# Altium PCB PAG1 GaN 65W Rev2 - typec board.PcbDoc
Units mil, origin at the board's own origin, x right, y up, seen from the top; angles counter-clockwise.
Board outline 312.28 x 580.71 mil, 2 copper layers (Top Layer, Bottom Layer); 6 components, 7 nets, 33 pads, 10 vias.
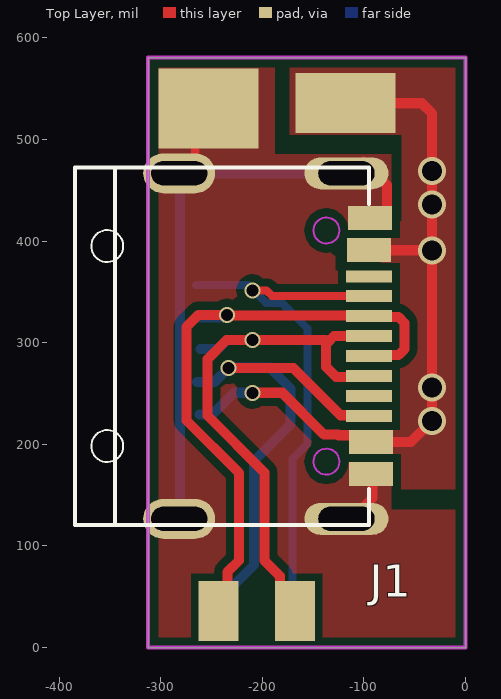
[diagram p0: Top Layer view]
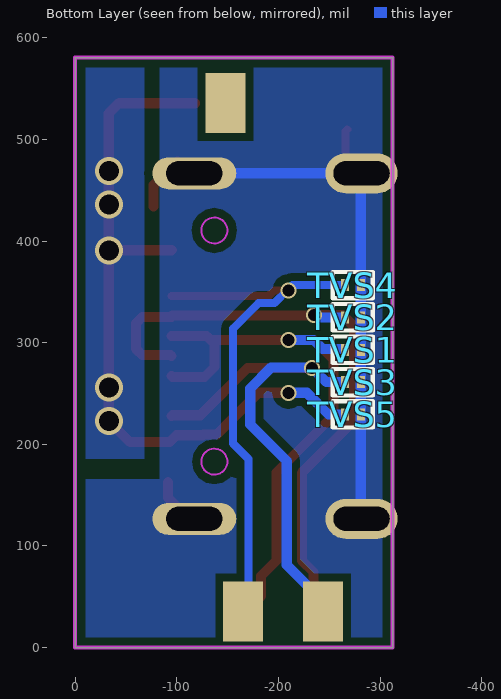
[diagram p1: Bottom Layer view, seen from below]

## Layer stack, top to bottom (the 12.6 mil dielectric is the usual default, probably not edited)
Top Solder: solder mask 0.4, Solder Resist, Dk 3.5
Top Layer: signal copper 1.4
Dielectric 1: dielectric 12.6, FR-4, Dk 4.8
Bottom Layer: signal copper 1.4
Bottom Solder: solder mask 0.4, Solder Resist, Dk 3.5

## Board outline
-312.28,0 -312.28,580.71 0,580.71 0,0

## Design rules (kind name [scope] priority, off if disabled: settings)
Clearance [All] p1: gap=8 ignorepadtopadclearanceinfootprint=FALSE
PlaneConnect [All] p1: planeconnectstyle=Direct reliefexpansion=20 reliefentries=4 reliefconductorwidth=10 reliefairgap=10
PolygonConnect [All] p1: connectstyle=Direct reliefconductorwidth=10 reliefentries=4 polygonreliefangle="90 Angle" airgapwidth=10
RoutingVias [All] p1: holewidth=28 width=50 viastyle="Through Hole" minholewidth=28 minwidth=50 maxholewidth=28 maxwidth=50
SolderMaskExpansion [All] p1: expansion=4 istentingtop=FALSE
UnRoutedNet [All] p1: checkbadconnections=TRUE
Width [All] p1: maxlimit=50 minlimit=6 preferedwidth=10 minimp=50.000000 maximp=50.000000 favimp=50.000000
28 further rules are at their usual default settings.

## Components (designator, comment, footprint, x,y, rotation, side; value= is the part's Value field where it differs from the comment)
J1 "" type-c3 -117.13,467.11 r180 top
TVS1 "ESD132 0201" W0201 -265.28,293.07 r180 bottom
TVS2 "ESD132 0201" W0201 -265.28,324.92 r180 bottom
TVS3 "ESD132 0201" W0201 -265.28,261.22 r180 bottom
TVS4 "ESD132 0201" W0201 -265.28,356.77 r180 bottom
TVS5 "ESD239 0201" W0201 -265.28,229.37 r180 bottom

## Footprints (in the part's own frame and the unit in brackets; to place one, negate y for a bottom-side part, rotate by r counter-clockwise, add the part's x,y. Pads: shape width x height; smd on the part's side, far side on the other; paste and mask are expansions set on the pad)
type-c3 [mm]
  rect 1.1x0.6 smd: A1(-0.588,1.129) A4(-0.563,1.929) B1(-0.613,7.529) B4(-0.613,6.729)
  rect 1.15x0.3 smd: A5(-0.563,3.079) A6(-0.563,4.079) A7(-0.563,4.579) A8(-0.563,5.579) B5(-0.563,6.079) B6(-0.563,5.079) B7(-0.563,3.579) B8(-0.563,2.594)
  oval 2.1x0.8 hole 0.6 slot 1.4 at 0 deg: MH1(0.002,8.649) MH4(0.002,0.009)
  oval 1.8x1 hole 0.6 slot 1.4 at 0 deg: MH2(4.182,8.649) MH3(4.182,0.009)
  Keep-Out Layer circle w0.05: c0.502,7.219 r0.325
  Keep-Out Layer circle w0.05: c0.502,1.439 r0.325
  silkscreen extent -0.57,-0.14 6.78,8.8
W0201 [mm]
  rect 0.2x0.3 smd mask+0.051: 1(0,0) 2(0.4,0)
  silkscreen extent -0.3,-0.33 0.7,0.33

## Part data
J1: library part USB-PD_TYPE-C_7
TVS1 TVS2 TVS3 TVS4 TVS5: library part "TVS Diode_1"

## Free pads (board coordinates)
  rect 98.43x78.74 smd: 0(-252.99,530.71)
  rect 39.37x59.06 smd far side: 0(-244.09,35.43) 0(-165.35,35.43) 0(-147.99,535.71)
  rect 39.37x59.06 smd: 0(-242.99,35.71) 0(-167.99,35.71)
  rect 98.43x59.06 smd: 0(-117.99,535.71)

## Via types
v1: diameter 27.56, hole 19.68, Top Layer to Bottom Layer, 5 vias
v2: diameter 15.75, hole 11.81, Top Layer to Bottom Layer, 5 vias

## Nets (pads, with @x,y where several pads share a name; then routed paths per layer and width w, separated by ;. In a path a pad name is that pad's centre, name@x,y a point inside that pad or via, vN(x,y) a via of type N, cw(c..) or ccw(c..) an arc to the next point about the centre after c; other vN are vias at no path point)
NetD16_K: J1.B5 pad.0@-244.09,35.43 TVS3.1 | length 513.6
  Top Layer w10: v2(-233.27,275.18) -169.59,275.18 -122.98,228.58 -95.74,228.58 J1.B5
  Bottom Layer w10: TVS3.1@-264.21,261.22 -247.23,261.22 v2(-233.27,275.18) ; pad.0@-244.09,35.43 -244.09,45.28 -208.17,81.2 -208.17,183.61 -172.24,219.54 -172.24,254.96 -192.99,275.71 v2@-233.27,275.71
NetD17_K: J1.A5 pad.0@-165.35,35.43 TVS4.1 | length 531.7
  Top Layer w7.87: v2(-209.8,351.46) -195.87,351.46 -190.31,345.91 J1.A5
  Bottom Layer w7.87: TVS4.1 -213.88,356.77 -209.19,352.08 -196.19,339.08 -194.05,339.08 -180.61,339.08 -155.31,313.77 -155.31,200.87 -170.48,185.69 -170.48,40.56 pad.0@-165.35,35.43
NetDM_1: J1.A7 J1.B7 pad.0@-242.99,35.71 TVS2.1 | length 622
  Top Layer w9.84: pad.0@-242.99,35.71 -234.47,44.23 -234.47,74.23 -222.99,85.71 -222.99,171.94 -274.61,223.55 -274.61,315.68 -262.82,327.47 v2(-234.87,327.47) -234.24,326.84 -95.58,326.84 J1.B7 ; J1.B7@-95.94,326.22 -94.96,325.24 -65.81,325.24 -60.04,319.47 -60.04,293.6 -65.81,287.84 -93.98,287.84 J1.A7
  Bottom Layer w9.84: TVS2.1@-262.99,324.92 v2@-237.99,324.92
NetDP_1: J1.A6 J1.B6 pad.0@-167.99,35.71 TVS1.1 | length 580.7
  Top Layer w9.84: pad.0@-167.99,35.71 -182.76,50.47 -182.76,70.47 -197.99,85.71 -197.99,172.17 -254.06,228.24 -254.06,283.8 -235.12,302.74 v2(-209.8,302.74) -137.09,302.74 -135.12,300.77 ; J1.B6 -95.8,266.32 -127.24,266.32 -137.09,276.17 -137.09,298.8 -135.12,300.77 ; J1.A6 -129.35,306.54 -135.12,300.77
  Bottom Layer w10: -260.95,293.73 -243.47,293.73 -234.46,302.74 v2(-209.8,302.74)
PGND: J1.A1 J1.B1 J1.MH1 J1.MH2 J1.MH3 J1.MH4 pad.0@-252.99,530.71 TVS1.2 TVS2.2 TVS3.2 TVS4.2 TVS5.2 | length 662.9
  Top Layer w8: pad.0@-267.72,509.84 -266.02,508.15 J1.MH3@-266.02,454.39
  Top Layer w9.84: J1.MH1@-100.47,138.15 -91.54,147.09 J1.B1@-91.54,162.98 ; J1.MH4@-100.47,478.31 -77.24,455.08 J1.A1@-77.24,434.22
  Bottom Layer w10: J1.MH3 J1.MH4 ; J1.MH3@-281.02,465.71 TVS3.2 -281.02,127.8 -267.46,114.23 J1.MH2@-266.02,114.23 ; J1.MH3@-267.46,454.39 J1.MH3@-266.02,454.39
SR_VSS: pad.0@-147.99,535.71
VBUS_C: J1.A4 J1.B4 pad.0@-117.99,535.71 TVS5.1 | length 718.4
  Top Layer w10: v2@-207.99,250.71 -180.43,250.71 -139.42,209.69 -125.8,209.69 -124.99,208.89 -99.68,208.89 J1.B4 -53.8,202.2 v1(-32.99,223.02) v1(-32.99,255.99) v1(-32.99,390.71) ; pad.0@-117.99,535.71 -42.99,535.71 -32.99,525.71 v1(-32.99,469.08) v1(-32.99,436.11) v1(-32.99,390.71) ; J1.A4 -94.72,390.95 -33.23,390.95 v1(-32.99,390.71)
  Bottom Layer w10: TVS5.1@-261.65,229.37 -249.33,229.37 -227.95,250.75 v2(-209.8,250.75)
pads on no net: J1.A8 J1.B8

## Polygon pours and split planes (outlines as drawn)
PGND on Bottom Layer "PGND_L02_P007" (solid, pour order 7): -312.28,580.71 -82.99,580.71 -82.99,165.71 -2.99,165.71 -2.99,0.71 -312.99,0.71
VBUS_C on Bottom Layer "VBUS_C_L02_P004" (solid, pour order 4): -67.99,185.71 -67.99,580.71 -2.99,580.71 -2.99,185.71
VBUS_C on Top Layer "VBUS_C_L01_P005" (solid, pour order 5): -172.99,580.71 -172.99,504.71 -62.99,504.71 -62.99,420.71 -82.99,395.71 -82.99,155.71 2.01,155.71 2.01,580.71
PGND on Top Layer "PGND_L01_P006" (solid, pour order 6): -312.28,580.71 -187.99,580.71 -187.99,485.71 -72.99,485.71 -72.99,410.71 -127.99,410.71 -127.99,370.71 -72.99,370.71 -72.99,135.71 2.01,135.71 2.01,0.71 -312.99,0.71

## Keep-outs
Keep-Out Layer:
  lines w3.94: -312.28,580.71 -312.28,0 0,0 0,580.71 -311.57,580.71

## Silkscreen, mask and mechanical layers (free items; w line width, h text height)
Bottom Solder:
  lines w19.68: -291.34,417.32 -229.33,417.32 ; -281.5,517.72 -219.49,517.72 ; -281.5,552.17 -219.49,552.17 ; -122.05,214.57 -122.05,276.57 ; -122.05,314.96 -122.05,376.97 ; -82.68,27.56 -82.68,88.58 ; -81.69,281.5 -81.69,342.52 ; -81.69,371.06 -81.69,424.21 ; -81.69,503.94 -81.69,564.96 ; -80.71,187.99 -80.71,249.02 ; -54.13,26.57 -54.13,88.58 ; -53.15,280.51 -53.15,342.52 ; -53.15,502.95 -53.15,564.96 ; -25.59,26.57 -25.59,88.58 ; -24.61,280.51 -24.61,342.52 ; -24.61,502.95 -24.61,564.96

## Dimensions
54.13,581.69 to 71.85,-0.98 on Top Layer
-312.99,-20.67 to 0.98,-15.75 on Top Layer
